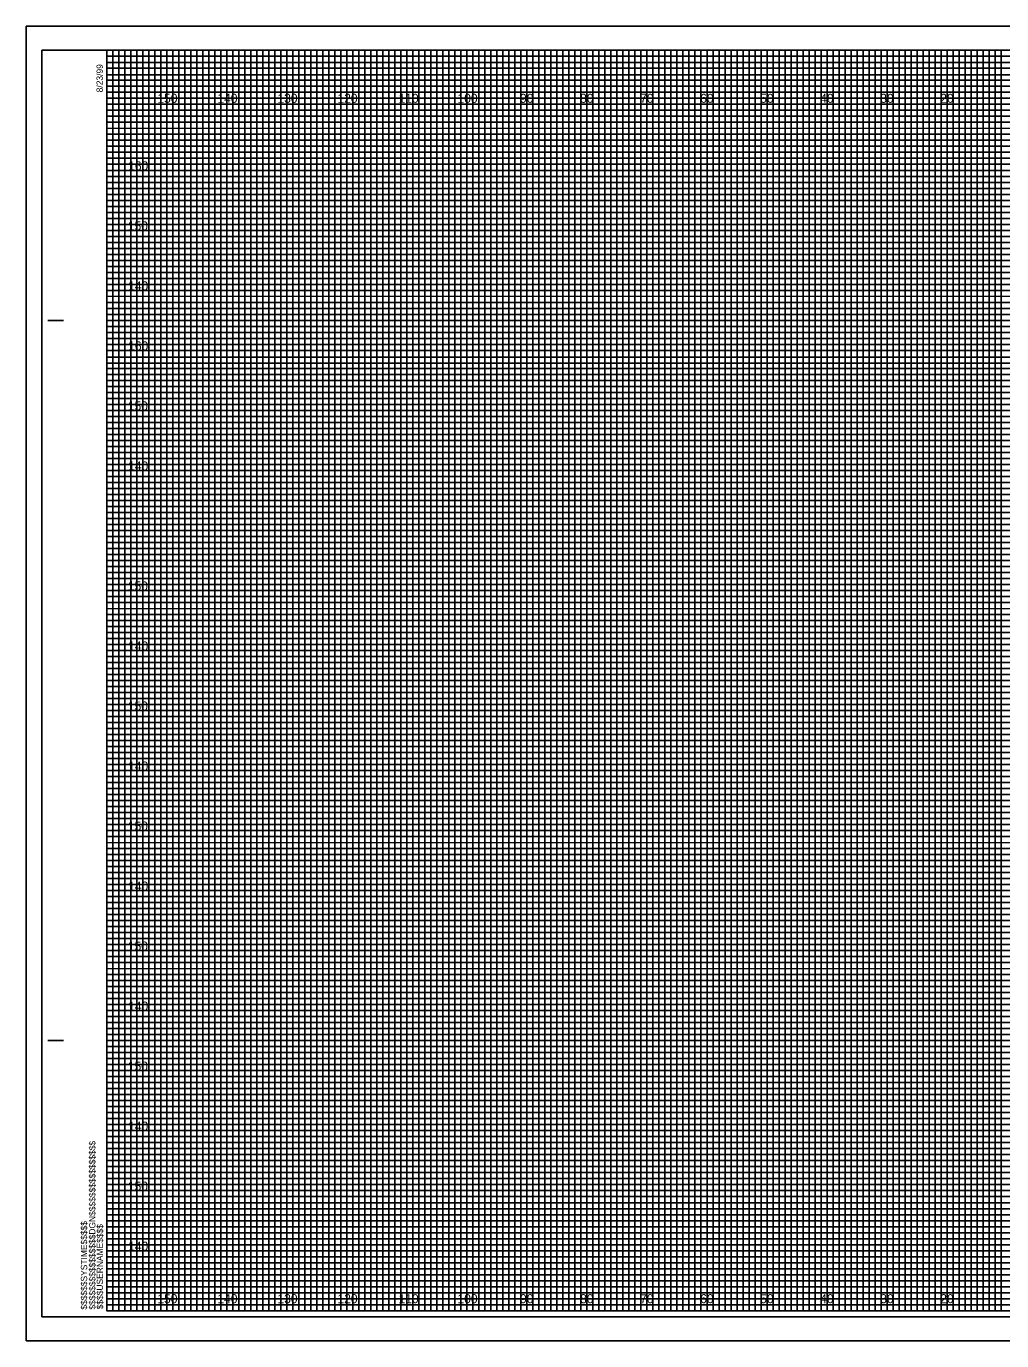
# Model space of a CAD drawing. Extents: x -13 to 323, y 215 to 434.
# Drawn here: x -13.4 to 149.1, y 215 to 434 of the extents above; entities that cross this region are included whole.
import ezdxf

# ---------------------------------------------------------------- set-up
doc = ezdxf.new("R2010")
doc.units = 0
for name, color, linetype in [('Exist Cross Section Cell', 7, 'Continuous'), ('Exist XS Center Line Elevation Label', 7, 'Continuous'), ('Exist XS Ground Line', 7, 'Continuous'), ('Prop CMT Pvmt Course 1', 7, 'Continuous'), ('Prop CMT Pvmt Course 3', 7, 'Continuous'), ('Prop CMT Pvmt Surface', 7, 'Continuous'), ('Prop CMT Pvmt Surface Shoulder', 7, 'Continuous'), ('Prop CMT Shld Paved Course 1', 7, 'Continuous'), ('Prop CMT Shld Paved Course 2', 7, 'Continuous'), ('Prop CMT Subgrade Earthwork', 7, 'Continuous'), ('Scratch_Level_2', 7, 'Continuous')]:
    doc.layers.add(name, color=color, linetype=linetype)

msp = doc.modelspace()

# ---------------------------------------------------------------- linework, layer by layer
at = {"layer": 'Exist XS Center Line Elevation Label'}
for points in [[(0, 430), (5, 430), (5, 220), (15, 220), (15, 430), (25, 430), (25, 220), (35, 220), (35, 430), (45, 430), (45, 220), (55, 220), (55, 430), (65, 430), (65, 220), (75, 220), (75, 430), (85, 430), (85, 220), (95, 220), (95, 430), (105, 430), (105, 220), (115, 220), (115, 430), (125, 430), (125, 220), (135, 220), (135, 430), (145, 430), (145, 220), (155, 220)], [(0, 425), (275, 425)], [(0, 405), (320, 405), (320, 415), (0, 415)], [(0, 385), (320, 385), (320, 395), (0, 395)], [(0, 365), (320, 365), (320, 375), (0, 375)], [(0, 345), (320, 345), (320, 355), (0, 355)], [(0, 325), (320, 325), (320, 335), (0, 335)], [(0, 305), (320, 305), (320, 315), (0, 315)], [(0, 285), (320, 285), (320, 295), (0, 295)], [(0, 265), (320, 265), (320, 275), (0, 275)], [(0, 245), (320, 245), (320, 255), (0, 255)], [(0, 225), (320, 225), (320, 235), (0, 235)]]:
    msp.add_lwpolyline(points, dxfattribs=at)
at = {"layer": 'Exist XS Ground Line'}
for p, q in [((10, 430), (0, 430)), ((10, 220), (10, 430)), ((30, 430), (20, 430)), ((20, 430), (20, 220)), ((30, 220), (30, 430)), ((50, 430), (40, 430)), ((40, 430), (40, 220)), ((50, 220), (50, 430)), ((70, 430), (60, 430)), ((60, 430), (60, 220)), ((70, 220), (70, 430)), ((90, 430), (80, 430)), ((80, 430), (80, 220)), ((90, 220), (90, 430)), ((110, 430), (100, 430)), ((100, 430), (100, 220)), ((110, 220), (110, 430)), ((130, 430), (120, 430)), ((120, 430), (120, 220)), ((130, 220), (130, 430)), ((150, 430), (140, 430)), ((140, 430), (140, 220)), ((20, 220), (10, 220)), ((40, 220), (30, 220)), ((60, 220), (50, 220)), ((80, 220), (70, 220)), ((100, 220), (90, 220)), ((120, 220), (110, 220)), ((140, 220), (130, 220))]:
    msp.add_line(p, q, dxfattribs=at)
for points in [[(0, 420), (320, 420), (320, 410), (0, 410)], [(0, 400), (320, 400), (320, 390), (0, 390)], [(0, 380), (320, 380), (320, 370), (0, 370)], [(0, 360), (320, 360), (320, 350), (0, 350)], [(0, 340), (320, 340), (320, 330), (0, 330)], [(0, 320), (320, 320), (320, 310), (0, 310)], [(0, 300), (320, 300), (320, 290), (0, 290)], [(0, 280), (320, 280), (320, 270), (0, 270)], [(0, 260), (320, 260), (320, 250), (0, 250)], [(0, 240), (320, 240), (320, 230), (0, 230)]]:
    msp.add_lwpolyline(points, dxfattribs=at)
at = {"layer": 'Prop CMT Pvmt Course 1'}
for p, q in [((323.3, 434), (-13.4, 434)), ((-13.4, 434), (-13.4, 215)), ((-13.4, 215), (323.3, 215))]:
    msp.add_line(p, q, dxfattribs=at)
at = {"layer": 'Prop CMT Pvmt Surface'}
msp.add_lwpolyline([(-10.8, 219), (322.4, 219), (322.4, 430), (-10.8, 430)], close=True, dxfattribs=at)
at = {"layer": 'Prop CMT Pvmt Surface Shoulder'}
for p, q in [((10, 220), (10, 430)), ((20, 220), (20, 430)), ((30, 220), (30, 430)), ((40, 220), (40, 430)), ((50, 220), (50, 430)), ((60, 220), (60, 430)), ((70, 220), (70, 430)), ((80, 220), (80, 430)), ((90, 220), (90, 430)), ((100, 220), (100, 430)), ((110, 220), (110, 430)), ((120, 220), (120, 430)), ((130, 220), (130, 430)), ((140, 220), (140, 430)), ((0, 420), (320, 420)), ((0, 410), (320, 410)), ((0, 400), (320, 400)), ((0, 390), (320, 390)), ((0, 380), (320, 380)), ((0, 370), (320, 370)), ((0, 360), (320, 360)), ((0, 350), (320, 350)), ((0, 340), (320, 340)), ((0, 330), (320, 330)), ((0, 320), (320, 320)), ((0, 310), (320, 310)), ((0, 300), (320, 300)), ((0, 290), (320, 290)), ((0, 280), (320, 280)), ((0, 270), (320, 270)), ((0, 260), (320, 260)), ((0, 250), (320, 250)), ((0, 240), (320, 240)), ((0, 230), (320, 230))]:
    msp.add_line(p, q, dxfattribs=at)
at = {"layer": 'Prop CMT Shld Paved Course 1'}
for p, q in [((-9.8, 385), (-7.3, 385)), ((-9.7, 385), (-7.2, 385)), ((-9.8, 265), (-7.3, 265)), ((-9.7, 265), (-7.2, 265)), ((0, 220), (0, 220)), ((0, 220), (0, 220)), ((0, 220), (0, 220)), ((0, 220), (0, 220)), ((0, 220), (0, 220)), ((0, 220), (0, 220)), ((0, 220), (0, 220))]:
    msp.add_line(p, q, dxfattribs=at)
msp.add_lwpolyline([(320, 430), (0, 430), (0, 220), (320, 220)], close=True, dxfattribs=at)
at = {"layer": 'Prop CMT Shld Paved Course 2'}
for points in [[(0, 220), (1, 220), (1, 430), (2, 430), (2, 220)], [(2, 220), (3, 220), (3, 430), (4, 430), (4, 220)], [(5, 220), (6, 220), (6, 430), (7, 430), (7, 220)], [(7, 220), (8, 220), (8, 430), (9, 430), (9, 220)], [(10, 220), (11, 220), (11, 430), (12, 430), (12, 220)], [(12, 220), (13, 220), (13, 430), (14, 430), (14, 220)], [(15, 220), (16, 220), (16, 430), (17, 430), (17, 220)], [(17, 220), (18, 220), (18, 430), (19, 430), (19, 220)], [(20, 220), (21, 220), (21, 430), (22, 430), (22, 220)], [(22, 220), (23, 220), (23, 430), (24, 430), (24, 220)], [(25, 220), (26, 220), (26, 430), (27, 430), (27, 220)], [(27, 220), (28, 220), (28, 430), (29, 430), (29, 220)], [(30, 220), (31, 220), (31, 430), (32, 430), (32, 220)], [(32, 220), (33, 220), (33, 430), (34, 430), (34, 220)], [(35, 220), (36, 220), (36, 430), (37, 430), (37, 220)], [(37, 220), (38, 220), (38, 430), (39, 430), (39, 220)], [(40, 220), (41, 220), (41, 430), (42, 430), (42, 220)], [(42, 220), (43, 220), (43, 430), (44, 430), (44, 220)], [(45, 220), (46, 220), (46, 430), (47, 430), (47, 220)], [(47, 220), (48, 220), (48, 430), (49, 430), (49, 220)], [(50, 220), (51, 220), (51, 430), (52, 430), (52, 220)], [(52, 220), (53, 220), (53, 430), (54, 430), (54, 220)], [(55, 220), (56, 220), (56, 430), (57, 430), (57, 220)], [(57, 220), (58, 220), (58, 430), (59, 430), (59, 220)], [(60, 220), (61, 220), (61, 430), (62, 430), (62, 220)], [(62, 220), (63, 220), (63, 430), (64, 430), (64, 220)], [(65, 220), (66, 220), (66, 430), (67, 430), (67, 220)], [(67, 220), (68, 220), (68, 430), (69, 430), (69, 220)], [(70, 220), (71, 220), (71, 430), (72, 430), (72, 220)], [(72, 220), (73, 220), (73, 430), (74, 430), (74, 220)], [(75, 220), (76, 220), (76, 430), (77, 430), (77, 220)], [(77, 220), (78, 220), (78, 430), (79, 430), (79, 220)], [(80, 220), (81, 220), (81, 430), (82, 430), (82, 220)], [(82, 220), (83, 220), (83, 430), (84, 430), (84, 220)], [(85, 220), (86, 220), (86, 430), (87, 430), (87, 220)], [(87, 220), (88, 220), (88, 430), (89, 430), (89, 220)], [(90, 220), (91, 220), (91, 430), (92, 430), (92, 220)], [(92, 220), (93, 220), (93, 430), (94, 430), (94, 220)], [(95, 220), (96, 220), (96, 430), (97, 430), (97, 220)], [(97, 220), (98, 220), (98, 430), (99, 430), (99, 220)], [(100, 220), (101, 220), (101, 430), (102, 430), (102, 220)], [(102, 220), (103, 220), (103, 430), (104, 430), (104, 220)], [(105, 220), (106, 220), (106, 430), (107, 430), (107, 220)], [(107, 220), (108, 220), (108, 430), (109, 430), (109, 220)], [(110, 220), (111, 220), (111, 430), (112, 430), (112, 220)], [(112, 220), (113, 220), (113, 430), (114, 430), (114, 220)], [(115, 220), (116, 220), (116, 430), (117, 430), (117, 220)], [(117, 220), (118, 220), (118, 430), (119, 430), (119, 220)], [(120, 220), (121, 220), (121, 430), (122, 430), (122, 220)], [(122, 220), (123, 220), (123, 430), (124, 430), (124, 220)], [(125, 220), (126, 220), (126, 430), (127, 430), (127, 220)], [(127, 220), (128, 220), (128, 430), (129, 430), (129, 220)], [(130, 220), (131, 220), (131, 430), (132, 430), (132, 220)], [(132, 220), (133, 220), (133, 430), (134, 430), (134, 220)], [(135, 220), (136, 220), (136, 430), (137, 430), (137, 220)], [(137, 220), (138, 220), (138, 430), (139, 430), (139, 220)], [(140, 220), (141, 220), (141, 430), (142, 430), (142, 220)], [(142, 220), (143, 220), (143, 430), (144, 430), (144, 220)], [(145, 220), (146, 220), (146, 430), (147, 430), (147, 220)], [(147, 220), (148, 220), (148, 430), (149, 430), (149, 220)]]:
    msp.add_lwpolyline(points, dxfattribs=at)
at = {"layer": 'Prop CMT Subgrade Earthwork'}
msp.add_lwpolyline([(-13.4, 215), (323.3, 215), (323.3, 434), (-13.4, 434)], close=True, dxfattribs=at)
at = {"layer": 'Scratch_Level_2'}
for p, q in [((0, 429), (260, 429)), ((260, 427.98), (0, 427.98)), ((0, 427.98), (0, 427)), ((0, 427), (260, 427)), ((260, 425.89), (0, 425.89)), ((0, 425.89), (0, 424)), ((0, 424), (320, 424))]:
    msp.add_line(p, q, dxfattribs=at)
for points in [[(0, 423), (270, 423), (320, 423), (320, 422), (0, 422)], [(0, 421), (320, 421), (320, 419), (0, 419)], [(0, 418), (320, 418), (320, 417), (0, 416.98)], [(0, 416), (320, 416), (320, 414), (0, 414)], [(0, 413), (320, 413), (320, 412), (0, 412)], [(0, 411), (320, 411), (320, 409), (0, 409)], [(0, 408), (320, 408), (320, 407), (0, 407)], [(0, 406), (320, 406), (320, 404), (0, 404)], [(0, 403), (320, 403), (320, 402), (0, 402)], [(0, 401), (320, 401), (320, 399), (0, 399)], [(0, 398), (320, 398), (320, 397), (0, 397)], [(0, 396), (320, 396), (320, 393.95), (320, 393), (320, 392), (0, 392)], [(0, 394), (320, 394), (320, 393), (0, 393)], [(0, 391), (320, 391), (320, 389), (0, 389.03)], [(0, 389.03), (320, 389), (320, 388), (0, 388)], [(0, 387), (320, 387), (320, 386), (0, 386)], [(0, 384), (320, 384), (320, 383), (0, 383)], [(0, 382), (320, 382), (320, 381), (0, 381)], [(-0.07, 378.89), (320, 378.89), (320, 377.88), (-0.07, 377.88)], [(0, 377), (320, 377), (320, 376), (0, 376)], [(0, 374), (320, 374), (320, 373), (0, 373)], [(0, 372), (320, 372), (320, 371), (0, 371)], [(0, 369), (320, 369), (320, 368), (0, 368)], [(0, 367), (320, 367), (320, 366), (0, 366)], [(0, 364), (320, 364), (320, 363), (0, 363)], [(0, 362), (320, 362), (320, 361), (0, 361)], [(0, 359), (320, 359), (319.99, 357.98), (0, 358)], [(0, 357), (320, 357), (320, 356), (0, 356)], [(0, 354), (320, 354), (320, 353), (0, 353)], [(0, 352), (320, 352), (320, 351), (0, 351)], [(0, 349), (320, 349), (320, 348), (0, 348)], [(0, 347), (320, 347), (320, 346), (0, 346)], [(0, 344), (320, 344), (320, 343), (0, 343)], [(0, 342), (320, 342), (320, 341), (0, 341)], [(0, 339), (320, 339), (320, 338), (0, 338)], [(0, 336.99), (320.07, 336.91), (320, 336), (0, 336)], [(0, 334), (320, 334), (320, 333), (0, 333)], [(0, 332), (320, 332), (320, 331), (0, 331)], [(0, 329), (320, 329), (320, 328), (0, 328)], [(0, 327), (320, 327), (320, 326), (0, 326)], [(0, 324), (320, 324), (320, 323), (0, 323)], [(0, 322), (320, 322), (320, 321), (0, 321)], [(0, 319), (320, 319), (320, 318), (0, 318)], [(0, 317), (320, 317), (320, 316), (0, 316)], [(0, 314), (320, 314), (320, 313), (0, 313)], [(0, 312), (320, 312), (320, 311), (0, 311)], [(0, 309), (320, 309), (320, 308), (0, 308)], [(0, 307), (320, 307), (320, 306), (0, 306)], [(0, 304), (320, 304), (320, 303), (0, 303)], [(0, 302), (320, 302), (320, 301), (0, 301)], [(0, 299), (320, 299), (319.99, 297.98), (0, 298)], [(0, 297), (320, 297), (320, 296), (0, 296)], [(0, 294), (320, 294), (320, 293), (0, 293)], [(0, 292), (320, 292), (320, 291), (0, 291)], [(0, 289), (320, 289), (320, 288), (0, 288)], [(0, 287), (320, 287), (320, 286), (0, 286)], [(0, 284), (320, 284), (320, 283), (0, 283)], [(0, 282), (320, 282), (320, 281), (0, 281)], [(0, 279), (320, 279), (320, 278), (0, 278)], [(0, 276.99), (320.07, 276.91), (320, 276), (0, 276)], [(0, 274), (320, 274), (320, 273), (0, 273)], [(0, 272), (320, 272), (320, 271), (0, 271)], [(0, 269), (320, 269), (320, 268), (0, 268)], [(0, 267), (320, 267), (320, 266), (0, 266)], [(0, 264), (320, 264), (320, 263), (0, 263)], [(0, 262), (320, 262), (320, 261), (0, 261)], [(0, 259), (320, 259), (320, 258), (0, 258)], [(0, 257), (320, 257), (320, 256), (0, 256)], [(0, 254), (320, 254), (320, 253), (0, 253)], [(0, 252), (320, 252), (320, 251), (0, 251)], [(0, 249), (320, 249), (320, 248), (0, 248)], [(0, 247), (320, 247), (320, 246), (0, 246)], [(0, 244), (320, 244), (320, 243), (0, 243)], [(0, 242), (320, 242), (320, 241), (0, 241)], [(0, 239), (320, 239), (320, 238), (0, 238)], [(0, 237), (320, 237), (320, 236), (0, 236)], [(0, 234), (320, 234), (320, 233), (0, 233)], [(0, 232), (320, 232), (320, 231), (0, 231)], [(0, 229), (320, 229), (320, 228), (0, 228)], [(0, 227), (320, 227), (320, 226), (0, 226)], [(0, 224), (320, 224), (320, 223), (0, 223)], [(0, 222), (320, 222), (320, 221), (0, 221)]]:
    msp.add_lwpolyline(points, dxfattribs=at)

# ---------------------------------------------------------------- texts
at = {"layer": 'Exist Cross Section Cell'}
for s, p in [('150', (8.44, 421.25)), ('140', (18.44, 421.25)), ('130', (28.44, 421.25)), ('120', (38.44, 421.25)), ('110', (48.62, 421.25)), ('100', (58.44, 421.25)), ('90', (68.86, 421.25)), ('80', (78.86, 421.25)), ('70', (88.86, 421.25)), ('60', (98.86, 421.25)), ('50', (108.86, 421.25)), ('40', (118.86, 421.25)), ('30', (128.86, 421.25)), ('20', (138.86, 421.25)), ('150', (8.44, 221.25)), ('140', (18.44, 221.25)), ('130', (28.44, 221.25)), ('120', (38.44, 221.25)), ('110', (48.62, 221.25)), ('100', (58.44, 221.25)), ('90', (68.86, 221.25)), ('80', (78.86, 221.25)), ('70', (88.86, 221.25)), ('60', (98.86, 221.25)), ('50', (108.86, 221.25)), ('40', (118.86, 221.25)), ('30', (128.86, 221.25)), ('20', (138.86, 221.25))]:
    msp.add_text(s, height=1.5, dxfattribs=at).set_placement(p)
at = {"layer": 'Prop CMT Pvmt Course 3'}
for s, p in [('160', (3.57, 410)), ('150', (3.52, 400)), ('140', (3.57, 390)), ('160', (3.57, 380)), ('150', (3.52, 370)), ('140', (3.57, 360)), ('150', (3.52, 340)), ('140', (3.57, 330)), ('150', (3.52, 320)), ('140', (3.57, 310)), ('150', (3.52, 300)), ('140', (3.57, 290)), ('150', (3.52, 280)), ('140', (3.57, 270)), ('150', (3.52, 260)), ('140', (3.57, 250)), ('150', (3.52, 240)), ('140', (3.57, 230))]:
    msp.add_text(s, height=1.5, dxfattribs=at).set_placement(p)
at = {"layer": 'Prop CMT Shld Paved Course 1'}
for s, p in [('8/23/99', (-0.65, 423)), ('$$$$$$$$$$$$$$$$DGN$$$$$$$$$$$$$$$$', (-1.88, 220.18)), ('$$$$$$SYSTIME$$$$$', (-3.26, 220.18)), ('$$$$USERNAME$$$$', (-0.62, 220.23))]:
    msp.add_text(s, height=1.05, rotation=90, dxfattribs=at).set_placement(p)

doc.saveas('drawing.dxf')
